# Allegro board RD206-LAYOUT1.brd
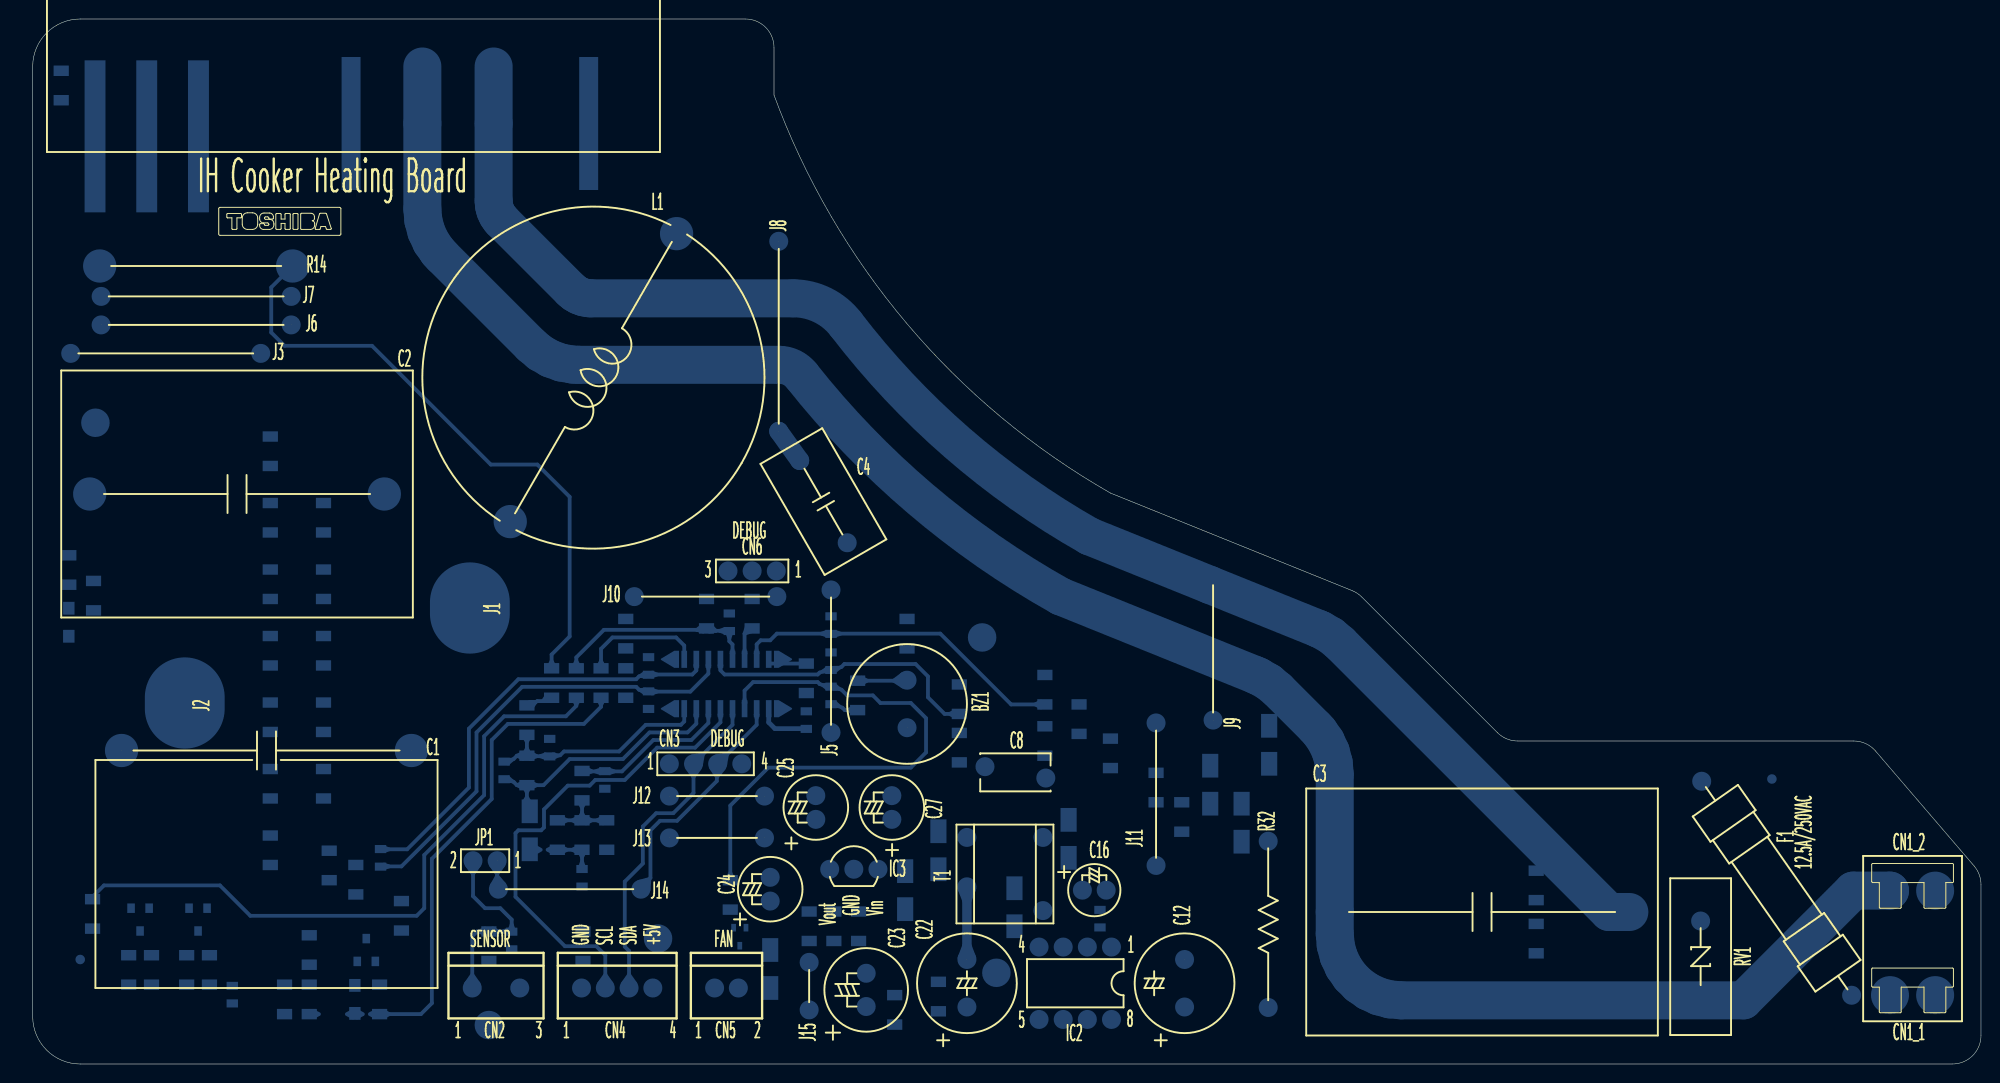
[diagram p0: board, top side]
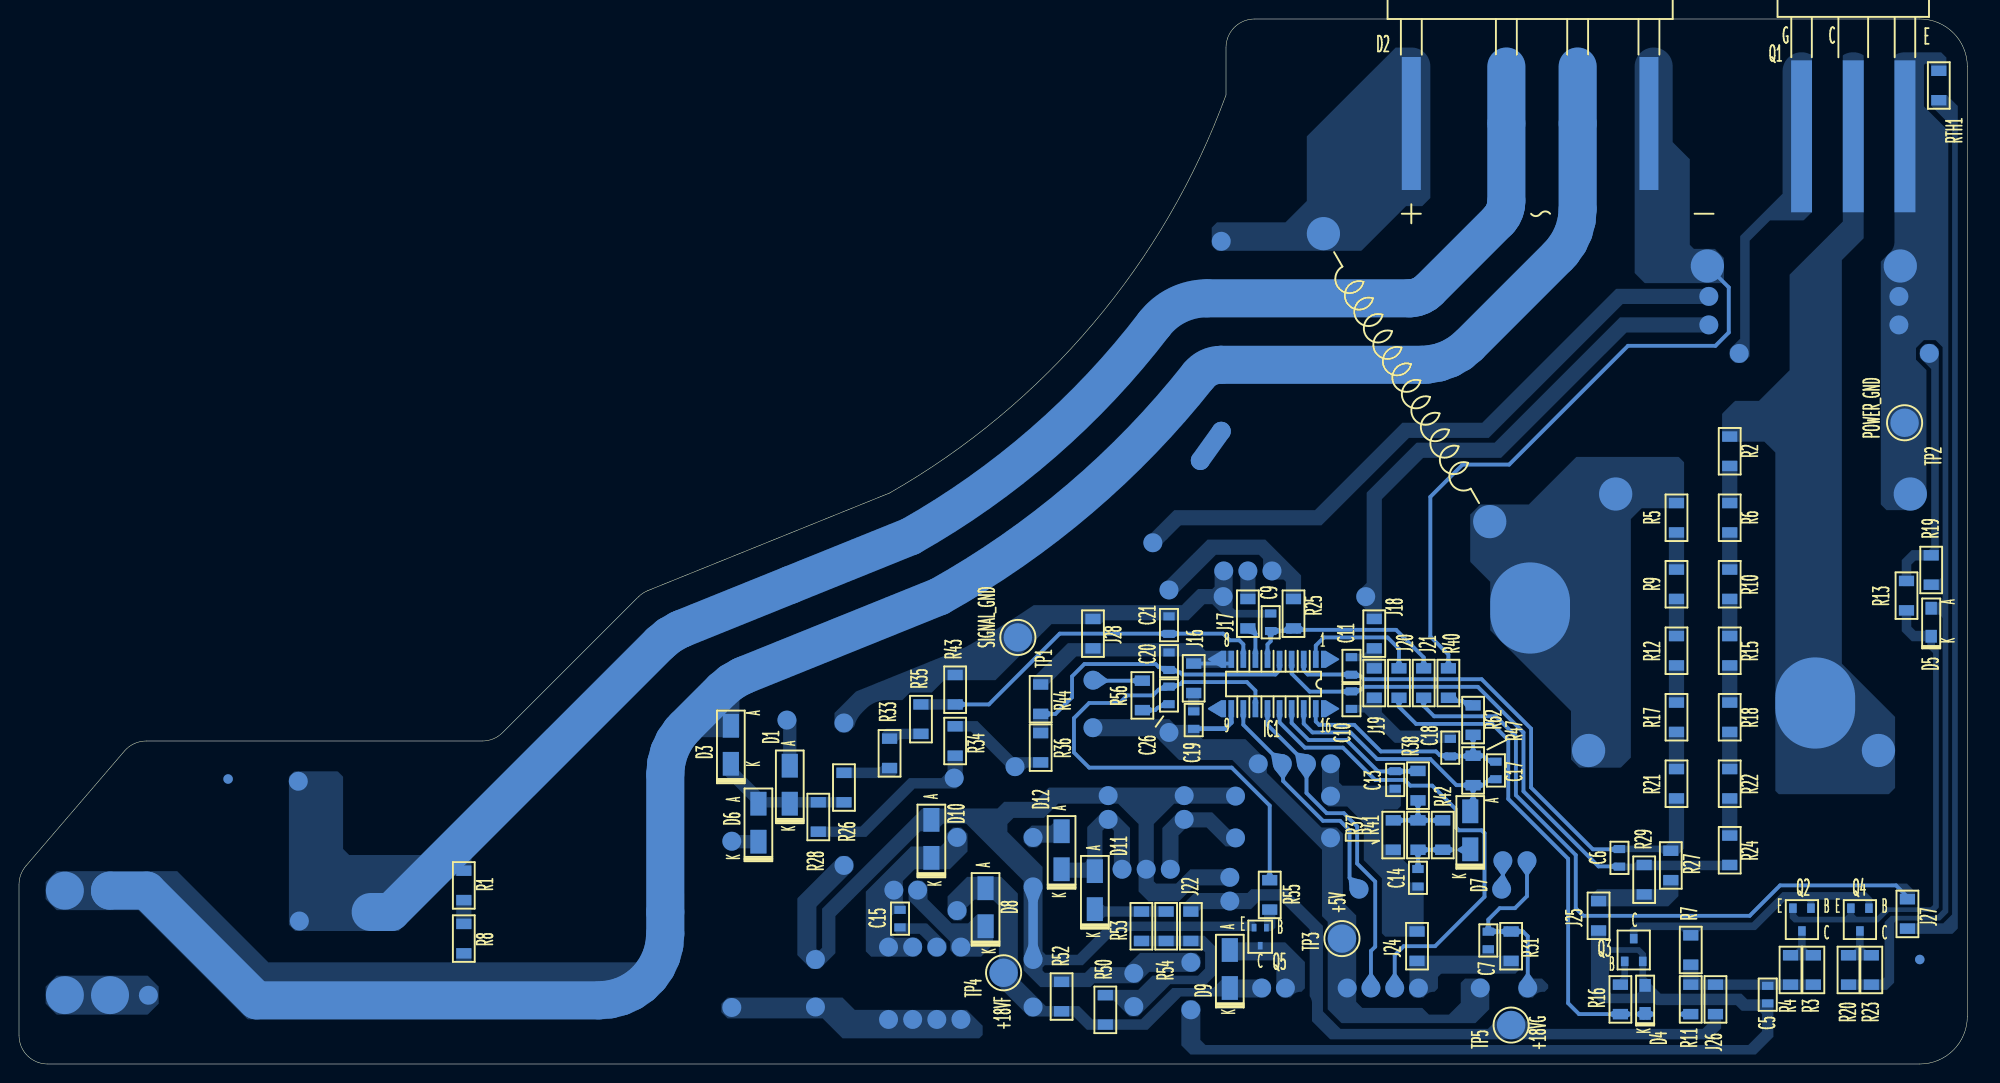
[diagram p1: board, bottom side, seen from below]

Outline 205 x 110 mm; copper layers: TOP, BOTTOM. Coordinates in mm from the lower left corner of the outline.
Outline path: 0,105 arc(1.46,108.54) 5,110 75,110 arc(77.12,109.12) 78,107 78,102 arc(92,77.92) 113.4,60.1 138.83,49.83 arc(139.37,49.55) 139.83,49.17 154.12,34.88 arc(155.09,34.23) 156.24,34 191.62,34 arc(192.87,33.73) 193.9,32.95 204.28,20.84 arc(204.81,19.93) 205,18.89 205,3 arc(204.12,0.88) 202,0 5,0 arc(1.46,1.46) 0,5 0,105

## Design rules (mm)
constraint set DEFAULT: 

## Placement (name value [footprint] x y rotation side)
BZ1  -  [FOOT13801A]  92 37.9 90 top
C1  -  [FOOT13608A]  24.6 33 180 top
C2  -  [FOOT13609A]  21.5 60 180 top
C3  -  [FOOT13609A]  152.5 16 180 top
C4  -  [FOOT13606A]  83.2 59.2 300 top
C5  -  [FOOT6003A]  21 7.3 270 bottom
C6  -  [FOOT6003A]  36.6 21.7 270 bottom
C7  -  [FOOT6003A]  50.4 13 90 bottom
C8  -  [FOOT13607A]  103.4 30.7 180 top
C9  -  [FOOT6003A]  73.3 46.5 90 bottom
C10  -  [FOOT6003A]  64.8 38.3 270 bottom
C11  -  [FOOT6003A]  64.8 41.9 90 bottom
C12  -  [FOOT13601A]  121.2 8.5 90 top
C13  -  [FOOT6003A]  60.2 29.9 270 bottom
C14  -  [FOOT6003A]  57.8 19.6 270 bottom
C15  -  [FOOT6003A]  112.3 15.3 270 bottom
C16  -  [FOOT13603A]  111.7 18.3 0 top
C17  -  [FOOT6003A]  49.6 30.9 90 bottom
C18  -  [FOOT6003A]  54.4 33.3 90 bottom
C19  -  [FOOT6003A]  81.4 36.2 90 bottom
C20  -  [FOOT6003A]  84 42.4 90 bottom
C21  -  [FOOT6003A]  84 46.2 90 bottom
C22  -  [FOOT13601A]  98.3 8.5 90 top
C23  -  [FOOT13604A]  87.7 7.8 90 top
C24  -  [FOOT13605A]  77.6 18.4 90 top
C25  -  [FOOT13605A]  82.4 27 90 top
C26  -  [FOOT6003A]  84 38.8 270 bottom
C27  -  [FOOT13605A]  90.4 27 90 top
CN1_1  -  [FOOT13901A]  197.8 7.25 0 top
CN1_2  -  [FOOT13901A]  197.8 18.25 0 top
CN2  -  [FOOT13910A]  48.75 8 180 top
CN3  -  [FOOT13906A]  70.8 31.6 0 top
CN4  -  [FOOT13904A]  61.5 8 180 top
CN5  -  [FOOT13902A]  73 8 180 top
CN6  -  [FOOT13908A]  75.7 51.9 180 top
D1  -  [FOOT13451A]  123.9 29.4 270 bottom
D2  -  [FOOT13452A]  46 121 180 bottom
D3  -  [FOOT13451A]  130.1 33.6 270 bottom
D4  -  [FOOT4291A]  33.9 6.8 270 bottom
D5  -  [FOOT4291A]  3.8 46.5 270 bottom
D6  -  [FOOT13451A]  127.2 25.4 270 bottom
D7  -  [FOOT13451A]  52.3 24.6 270 bottom
D8  -  [FOOT13451A]  103.3 16.5 270 bottom
D9  -  [FOOT13451A]  77.6 10 270 bottom
D10  -  [FOOT13451A]  109 23.7 270 bottom
D11  -  [FOOT13451A]  91.8 18.3 270 bottom
D12  -  [FOOT13451A]  95.3 22.5 270 bottom
F1  -  [FOOT13701A]  183.5 18.5 125 top
IC1  -  [FOOT2183A]  73 40 0 bottom
IC2  -  [FOOT13001A]  109.7 8.5 180 top
IC3  -  [FOOT13002A]  86.4 20.5 0 top
J1  -  [FOOT13909A]  46 48 0 top
J2  -  [FOOT13909A]  16 38 0 top
J3  -  [FOOT13917A]  24 74.8 180 top
J5  -  [FOOT13915A]  84 34.9 90 top
J6  -  [FOOT13917A]  7.2 77.8 0 top
J7  -  [FOOT13917A]  27.2 80.8 180 top
J8  -  [FOOT13917A]  78.5 86.6 270 top
J9  -  [FOOT13915A]  124.2 51.2 270 top
J10  -  [FOOT13915A]  63.3 49.2 0 top
J11  -  [FOOT13915A]  118.2 35.9 270 top
J12  -  [FOOT13913A]  77 28.2 180 top
J13  -  [FOOT13913A]  77 23.8 180 top
J14  -  [FOOT13915A]  64 18.4 180 top
J15  -  [FOOT13911A]  81.7 10.7 270 top
J16  -  [J16_FOOT4004B]  81.4 40.6 90 bottom
J17  -  [J17_FOOT4004B]  75.7 47.4 90 bottom
J18  -  [J18_FOOT4004B]  62.4 45.3 270 bottom
J19  -  [J19_FOOT4004B]  62.4 40.1 270 bottom
J20  -  [J20_FOOT4004B]  59.8 40.1 270 bottom
J21  -  [J21_FOOT4004B]  57.2 40.1 90 bottom
J22  -  [J22_FOOT4004B]  81.7 14.5 90 bottom
J24  -  [J24_FOOT4004B]  57.9 12.4 270 bottom
J25  -  [J25_FOOT4004B]  38.8 15.6 90 bottom
J26  -  [J26_FOOT4004B]  26.5 6.8 90 bottom
J27  -  [J27_FOOT4004B]  6.3 15.8 90 bottom
J28  -  [J28_FOOT4004B]  92 45.3 270 bottom
JP1  -  [FOOT13905A]  47.6 21.4 180 top
L1  -  [FOOT13301A]  59 72.25 240 top
NOREF  -  []  48.75 8 0 top
NOREF#2  -  []  70.15 6.4 0 top
NOREF#3  -  []  5 5 0 top
NOREF#4  -  []  44.65 6.4 0 top
NOREF#5  -  []  174 -14 0 top
NOREF#6  -  []  191 27 0 top
NOREF#7  -  []  25 103 0 top
NOREF#8  -  []  26 88.7 0 top
NOREF#9  -  []  56.15 6.4 0 top
NOREF#10  -  []  25 103 0 top
NOREF#11  -  []  191 27 0 top
NOREF#12  -  []  5 5 0 top
NOREF#13  -  []  183 30 180 bottom
NOREF#14  -  []  5 11 180 bottom
Q1  -  [FOOT13501A]  12 125 180 bottom
Q2  -  [FOOT5004A]  17.4 15.2 0 bottom
Q3  -  [FOOT5004A]  35.1 12 180 bottom
Q4  -  [FOOT5004A]  11.3 15.2 0 bottom
Q5  -  [FOOT13502A]  74.4 13.4 0 bottom
R1  -  [R1_FOOT4004B]  158.2 18.8 270 bottom
R2  -  [R2_FOOT4004B]  25 64.5 270 bottom
R3  -  [R3_FOOT4004B]  16.2 9.9 90 bottom
R4  -  [R4_FOOT4004B]  18.6 9.9 90 bottom
R5  -  [R5_FOOT4004B]  30.6 57.5 270 bottom
R6  -  [R6_FOOT4004B]  25 57.5 90 bottom
R7  -  [R7_FOOT4004B]  29.1 12 90 bottom
R8  -  [R8_FOOT4004B]  158.2 13.2 270 bottom
R9  -  [R9_FOOT4004B]  30.6 50.5 270 bottom
R10  -  [R10_FOOT4004B]  25 50.5 270 bottom
R11  -  [R11_FOOT4004B]  29.1 6.8 270 bottom
R12  -  [R12_FOOT4004B]  30.6 43.5 270 bottom
R13  -  [R13_FOOT4004B]  6.4 49.3 270 bottom
R14  -  [FOOT13402A]  17.2 84 180 top
R15  -  [R15_FOOT4004B]  25 43.5 270 bottom
R16  -  [R16_FOOT4004B]  36.5 6.8 270 bottom
R17  -  [R17_FOOT4004B]  30.6 36.5 270 bottom
R18  -  [R18_FOOT4004B]  25 36.5 270 bottom
R19  -  [R19_FOOT4004B]  3.8 52 270 bottom
R20  -  [R20_FOOT4004B]  12.5 9.9 270 bottom
R21  -  [R21_FOOT4004B]  30.6 29.5 270 bottom
R22  -  [R22_FOOT4004B]  25 29.5 270 bottom
R23  -  [R23_FOOT4004B]  10.1 9.9 270 bottom
R24  -  [R24_FOOT4004B]  25 22.5 270 bottom
R25  -  [R25_FOOT4004B]  70.9 47.4 270 bottom
R26  -  [R26_FOOT4004B]  118.2 29.1 90 bottom
R27  -  [R27_FOOT4004B]  31.2 20.9 270 bottom
R28  -  [R28_FOOT4004B]  120.9 26 270 bottom
R29  -  [R29_FOOT4004B]  34 19.4 270 bottom
R31  -  [R31_FOOT4004B]  48 12.4 90 bottom
R32  -  [FOOT13401A]  130 14.7 270 top
R33  -  [R33_FOOT4004B]  113.4 32.7 90 bottom
R34  -  [R34_FOOT4004B]  106.5 34 90 bottom
R35  -  [R35_FOOT4004B]  110.1 36.3 90 bottom
R36  -  [R36_FOOT4004B]  97.5 33.3 90 bottom
R37  -  [R37_FOOT4004B]  60.4 24.1 90 bottom
R38  -  [R38_FOOT4004B]  57.8 29.3 90 bottom
R40  -  [R40_FOOT4004B]  54.6 40.1 270 bottom
R41  -  [R41_FOOT4004B]  57.8 24.1 270 bottom
R42  -  [R42_FOOT4004B]  55.2 24.1 270 bottom
R43  -  [R43_FOOT4004B]  106.5 39.4 90 bottom
R44  -  [R44_FOOT4004B]  97.5 38.4 90 bottom
R47  -  [R47_FOOT4004B]  52 30.9 90 bottom
R50  -  [R50_FOOT4004B]  90.7 5.7 90 bottom
R52  -  [R52_FOOT4004B]  95.3 7.1 90 bottom
R53  -  [R53_FOOT4004B]  86.9 14.5 90 bottom
R54  -  [R54_FOOT4004B]  84.3 14.5 90 bottom
R55  -  [R55_FOOT4004B]  73.4 17.8 270 bottom
R56  -  [R56_FOOT4004B]  86.8 38.8 90 bottom
R62  -  [R62_FOOT4004B]  52 36.2 270 bottom
RTH1  -  [FOOT3109A]  3 103 270 bottom
RV1  -  [FOOT13302A]  175.5 11.3 270 top
T1  -  [FOOT13303A]  102.3 20 270 top
TP1  -  [FOOT13998A]  99.9 44.9 180 bottom
TP2  -  [FOOT13998A]  6.6 67.5 180 bottom
TP3  -  [FOOT13998A]  65.8 13.2 180 bottom
TP4  -  [FOOT13998A]  101.4 9.6 180 bottom
TP5  -  [FOOT13998A]  48 4.1 180 bottom

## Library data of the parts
BZ1 = Part13801: alternate symbols: (BZ1_Foot13801A)
C1 = Part13608: alternate symbols: (C1_Foot13608A)
C2 C3 = Part13609: alternate symbols: (C2_Foot13609A,C3_Foot13609A)
C4 = Part13606: alternate symbols: (C4_Foot13606A)
C5-C7 C9-C11 C13-C15 C17-C21 C26 = Part6003: alternate symbols: (T:Foot6003A;B:Foot6003B)
C8 = Part13607: alternate symbols: (C8_Foot13607A)
C12 C22 = Part13601: alternate symbols: (C22_Foot13601A,C12_Foot13601A)
C16 = Part13603: alternate symbols: (C16_Foot13603A)
C23 = Part13604: alternate symbols: (C23_Foot13604A)
C24 C25 C27 = Part13605: alternate symbols: (C24_Foot13605A,C25_Foot13605A,C27_Foot13605A)
CN1_1 CN1_2 = Part13901: alternate symbols: (CN1_1_Foot13901A,CN1_2_Foot13901A)
CN2 = Part13910: alternate symbols: (CN2_Foot13910A)
CN3 = Part13906: alternate symbols: (CN3_Foot13906A)
CN4 = Part13904: alternate symbols: (CN4_Foot13904A)
CN5 = Part13902: alternate symbols: (CN5_Foot13902A)
CN6 = Part13908: alternate symbols: (CN6_Foot13908A)
D1 D3 D6-D12 = Part13451: alternate symbols: (T:Foot13451A;B:Foot13451B,D1_Foot13451B,D3_Foot13451B,D6_Foot13451B,D7_Foot13451B,D8_Foot13451B,D9_Foot13451B,D10_Foot13451B,D11_Foot13451B,D12_Foot13451B)
D2 = Part13452: alternate symbols: (T:Foot13452A;B:Foot13452B,D2_Foot13452B)
D4 D5 = Part4291: alternate symbols: (T:Foot4291A;B:Foot4291B,D4_Foot4291B,D5_Foot4291B)
F1 = Part13701: alternate symbols: (F1_Foot13701A)
IC1 = Part2183: alternate symbols: (T:Foot2183A;B:Foot2183B,IC1_Foot2183B)
IC2 = Part13001: alternate symbols: (IC2_Foot13001A)
IC3 = Part13002: alternate symbols: (IC3_Foot13002A)
J1 J2 = Part13909: alternate symbols: (J1_Foot13909A,J2_Foot13909A)
J3 J6-J8 = Part13917: alternate symbols: (J3_Foot13917A,J6_Foot13917A,J7_Foot13917A,J8_Foot13917A)
J5 J9-J11 J14 = Part13915: alternate symbols: (J5_Foot13915A,J9_Foot13915A,J10_Foot13915A,J11_Foot13915A,J14_Foot13915A)
J12 J13 = Part13913: alternate symbols: (J12_Foot13913A,J13_Foot13913A)
J15 = Part13911: alternate symbols: (J15_Foot13911A)
J16-J22 J24-J28 R1-R13 R15-R29 R31 R33-R38 R40-R44 R47 R50 R52-R56 R62 = Part4004
JP1 = Part13905: alternate symbols: (JP1_Foot13905A)
L1 = Part13301: alternate symbols: (L1_Foot13301A)
Q1 = Part13501: alternate symbols: (T:Foot13501A;B:Foot13501B,Q1_Foot13501B)
Q2-Q4 = Part5004: alternate symbols: (T:Foot5004A;B:Foot5004B,Q2_Foot5004B,Q3_Foot5004B,Q4_Foot5004B)
Q5 = Part13502: alternate symbols: (T:Foot13502A;B:Foot13502B,Q5_Foot13502B)
R14 = Part13402: alternate symbols: (R14_Foot13402A)
R32 = Part13401: alternate symbols: (R32_Foot13401A)
RTH1 = Part3109: alternate symbols: (T:Foot3109A;B:Foot3109B,RTH1_Foot3109B)
RV1 = Part13302: alternate symbols: (RV1_Foot13302A)
T1 = Part13303: alternate symbols: (T1_Foot13303A)
TP1-TP5 = Part13998: alternate symbols: (T:Foot13998A;B:Foot13998B,TP1_Foot13998B,TP2_Foot13998B,TP3_Foot13998B,TP4_Foot13998B,TP5_Foot13998B)

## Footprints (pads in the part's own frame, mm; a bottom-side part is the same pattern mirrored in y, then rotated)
FOOT2183A
  rect 0.6x1.8 smd: 1(-4.445,-2.6) 2(-3.175,-2.6) 3(-1.905,-2.6) 4(-0.635,-2.6) 5(0.635,-2.6) 6(1.905,-2.6) 7(3.175,-2.6) 8(4.445,-2.6) 9(4.445,2.6) 10(3.175,2.6) 11(1.905,2.6) 12(0.635,2.6) 13(-0.635,2.6) 14(-1.905,2.6) 15(-3.175,2.6) 16(-4.445,2.6)
FOOT3109A
  rect 1.1x1.6 smd: 1(-1.55,0) 2(1.55,0)
FOOT4291A
  rect 1.35x1.2 smd: A(-1.475,0) C(1.475,0)
FOOT5004A
  rect 0.8x1 smd: 1(-0.95,-1.2) 2(0.95,-1.2) 3(0,1.2)
FOOT6003A
  rect 0.85x1.2 smd: 1(-0.925,0) 2(0.925,0)
FOOT13001A
  round 0.01 hole 0.9: 1(-3.81,-3.81) 2(-1.27,-3.81) 3(1.27,-3.81) 4(3.81,-3.81) 5(3.81,3.81) 6(1.27,3.81) 7(-1.27,3.81) 8(-3.81,3.81)
FOOT13002A
  round 0.01 hole 1: 1(-2.54,0) 2(0,0) 3(2.54,0)
FOOT13301A
  round 0.01 hole 1.3: 1(-17.5,0) 2(17.5,0)
FOOT13302A
  round 0.01 hole 1: 1(-3.75,0) 2(3.75,0)
FOOT13303A
  round 0.01 hole 0.9: 1(-3.85,-4) 3(1.35,-4) 5(3.85,4) 8(-3.85,4)
FOOT13401A
  round 0.01 hole 0.9: 1(-8.75,0) 2(8.75,0)
FOOT13402A
  round 0.01 hole 1.3: 1(-10.15,0) 2(10.15,0)
FOOT13451A
  rect 2.5x1.7 smd: A(-2,0) C(2,0)
FOOT13452A
  rect 2x14 smd: 1(-12.5,-22) 2(-2.5,-22) 3(5,-22) 4(12.5,-22)
FOOT13501A
  rect 2.2x16 smd: 1(-5.44,-27.35) 2(0,-27.35) 3(5.44,-27.35)
FOOT13502A
  rect 0.5x0.8 smd: 1(-0.65,-0.95) 2(0.65,-0.95) 3(0,0.95)
FOOT13601A
  round 0.01 hole 0.9: 1(-2.5,0) 2(2.5,0)
FOOT13603A
  round 0.01 hole 0.9: 1(-1.25,0) 2(1.25,0)
FOOT13604A
  round 0.01 hole 0.9: 1(-1.75,0) 2(1.75,0)
FOOT13605A
  round 0.01 hole 0.9: 1(-1.25,0) 2(1.25,0)
FOOT13606A
  round 0.01 hole 0.9: 1(-5,0) 2(5,0)
FOOT13607A
  round 0.01 hole 0.9: 1(-3.2,0.6) 2(3.2,-0.6)
FOOT13608A
  round 0.01 hole 1.3: 1(-15.25,0) 2(15.25,0)
FOOT13609A
  round 0.01 hole 1.3: 1(-15.5,0) 2(15.5,0)
FOOT13701A
  round 0.01 hole 1: 1(-13.75,0) 2(13.75,0)
FOOT13801A
  round 0.01 hole 0.9: 1(-2.5,0) 2(2.5,0)
FOOT13901A
  round 0.01 hole 1.7: 1(-2.375,0) 2(2.375,0)
FOOT13902A
  round 0.01 hole 1: 1(1.25,0) 2(-1.25,0)
FOOT13904A
  round 0.01 hole 1: 1(3.75,0) 2(1.25,0) 3(-1.25,0) 4(-3.75,0)
FOOT13905A
  round 0.01 hole 1: 1(-1.27,0) 2(1.27,0)
FOOT13906A
  round 0.01 hole 1: 1(-3.81,0) 2(-1.27,0) 3(1.27,0) 4(3.81,0)
FOOT13908A
  round 0.01 hole 1: 1(-2.54,0) 2(0,0) 3(2.54,0)
FOOT13909A
  round 0.01 hole 1.505: 1(0,0)
FOOT13910A
  round 0.01 hole 1: 1(2.5,0) 3(-2.5,0)
FOOT13911A
  round 0.01 hole 1: 1(0,0) 2(5,0)
FOOT13913A
  round 0.01 hole 1: 1(0,0) 2(10,0)
FOOT13915A
  round 0.01 hole 1: 1(0,0) 2(15,0)
FOOT13917A
  round 0.01 hole 1: 1(0,0) 2(20,0)
FOOT13998A
  round 3 smd: 1(0,0)
J16_FOOT4004B
  rect 1.1x1.6 smd: 1(-1.55,0) 2(1.55,0)
J17_FOOT4004B
  rect 1.1x1.6 smd: 1(-1.55,0) 2(1.55,0)
J18_FOOT4004B
  rect 1.1x1.6 smd: 1(-1.55,0) 2(1.55,0)
J19_FOOT4004B
  rect 1.1x1.6 smd: 1(-1.55,0) 2(1.55,0)
J20_FOOT4004B
  rect 1.1x1.6 smd: 1(-1.55,0) 2(1.55,0)
J21_FOOT4004B
  rect 1.1x1.6 smd: 1(-1.55,0) 2(1.55,0)
J22_FOOT4004B
  rect 1.1x1.6 smd: 1(-1.55,0) 2(1.55,0)
J24_FOOT4004B
  rect 1.1x1.6 smd: 1(-1.55,0) 2(1.55,0)
J25_FOOT4004B
  rect 1.1x1.6 smd: 1(-1.55,0) 2(1.55,0)
J26_FOOT4004B
  rect 1.1x1.6 smd: 1(-1.55,0) 2(1.55,0)
J27_FOOT4004B
  rect 1.1x1.6 smd: 1(-1.55,0) 2(1.55,0)
J28_FOOT4004B
  rect 1.1x1.6 smd: 1(-1.55,0) 2(1.55,0)
R1_FOOT4004B
  rect 1.1x1.6 smd: 1(-1.55,0) 2(1.55,0)
R2_FOOT4004B
  rect 1.1x1.6 smd: 1(-1.55,0) 2(1.55,0)
R3_FOOT4004B
  rect 1.1x1.6 smd: 1(-1.55,0) 2(1.55,0)
R4_FOOT4004B
  rect 1.1x1.6 smd: 1(-1.55,0) 2(1.55,0)
R5_FOOT4004B
  rect 1.1x1.6 smd: 1(-1.55,0) 2(1.55,0)
R6_FOOT4004B
  rect 1.1x1.6 smd: 1(-1.55,0) 2(1.55,0)
R7_FOOT4004B
  rect 1.1x1.6 smd: 1(-1.55,0) 2(1.55,0)
R8_FOOT4004B
  rect 1.1x1.6 smd: 1(-1.55,0) 2(1.55,0)
R9_FOOT4004B
  rect 1.1x1.6 smd: 1(-1.55,0) 2(1.55,0)
R10_FOOT4004B
  rect 1.1x1.6 smd: 1(-1.55,0) 2(1.55,0)
R11_FOOT4004B
  rect 1.1x1.6 smd: 1(-1.55,0) 2(1.55,0)
R12_FOOT4004B
  rect 1.1x1.6 smd: 1(-1.55,0) 2(1.55,0)
R13_FOOT4004B
  rect 1.1x1.6 smd: 1(-1.55,0) 2(1.55,0)
R15_FOOT4004B
  rect 1.1x1.6 smd: 1(-1.55,0) 2(1.55,0)
R16_FOOT4004B
  rect 1.1x1.6 smd: 1(-1.55,0) 2(1.55,0)
R17_FOOT4004B
  rect 1.1x1.6 smd: 1(-1.55,0) 2(1.55,0)
R18_FOOT4004B
  rect 1.1x1.6 smd: 1(-1.55,0) 2(1.55,0)
R19_FOOT4004B
  rect 1.1x1.6 smd: 1(-1.55,0) 2(1.55,0)
R20_FOOT4004B
  rect 1.1x1.6 smd: 1(-1.55,0) 2(1.55,0)
R21_FOOT4004B
  rect 1.1x1.6 smd: 1(-1.55,0) 2(1.55,0)
R22_FOOT4004B
  rect 1.1x1.6 smd: 1(-1.55,0) 2(1.55,0)
R23_FOOT4004B
  rect 1.1x1.6 smd: 1(-1.55,0) 2(1.55,0)
R24_FOOT4004B
  rect 1.1x1.6 smd: 1(-1.55,0) 2(1.55,0)
R25_FOOT4004B
  rect 1.1x1.6 smd: 1(-1.55,0) 2(1.55,0)
R26_FOOT4004B
  rect 1.1x1.6 smd: 1(-1.55,0) 2(1.55,0)
R27_FOOT4004B
  rect 1.1x1.6 smd: 1(-1.55,0) 2(1.55,0)
R28_FOOT4004B
  rect 1.1x1.6 smd: 1(-1.55,0) 2(1.55,0)
R29_FOOT4004B
  rect 1.1x1.6 smd: 1(-1.55,0) 2(1.55,0)
R31_FOOT4004B
  rect 1.1x1.6 smd: 1(-1.55,0) 2(1.55,0)
R33_FOOT4004B
  rect 1.1x1.6 smd: 1(-1.55,0) 2(1.55,0)
R34_FOOT4004B
  rect 1.1x1.6 smd: 1(-1.55,0) 2(1.55,0)
R35_FOOT4004B
  rect 1.1x1.6 smd: 1(-1.55,0) 2(1.55,0)
R36_FOOT4004B
  rect 1.1x1.6 smd: 1(-1.55,0) 2(1.55,0)
R37_FOOT4004B
  rect 1.1x1.6 smd: 1(-1.55,0) 2(1.55,0)
R38_FOOT4004B
  rect 1.1x1.6 smd: 1(-1.55,0) 2(1.55,0)
R40_FOOT4004B
  rect 1.1x1.6 smd: 1(-1.55,0) 2(1.55,0)
R41_FOOT4004B
  rect 1.1x1.6 smd: 1(-1.55,0) 2(1.55,0)
R42_FOOT4004B
  rect 1.1x1.6 smd: 1(-1.55,0) 2(1.55,0)
R43_FOOT4004B
  rect 1.1x1.6 smd: 1(-1.55,0) 2(1.55,0)
R44_FOOT4004B
  rect 1.1x1.6 smd: 1(-1.55,0) 2(1.55,0)
R47_FOOT4004B
  rect 1.1x1.6 smd: 1(-1.55,0) 2(1.55,0)
R50_FOOT4004B
  rect 1.1x1.6 smd: 1(-1.55,0) 2(1.55,0)
R52_FOOT4004B
  rect 1.1x1.6 smd: 1(-1.55,0) 2(1.55,0)
R53_FOOT4004B
  rect 1.1x1.6 smd: 1(-1.55,0) 2(1.55,0)
R54_FOOT4004B
  rect 1.1x1.6 smd: 1(-1.55,0) 2(1.55,0)
R55_FOOT4004B
  rect 1.1x1.6 smd: 1(-1.55,0) 2(1.55,0)
R56_FOOT4004B
  rect 1.1x1.6 smd: 1(-1.55,0) 2(1.55,0)
R62_FOOT4004B
  rect 1.1x1.6 smd: 1(-1.55,0) 2(1.55,0)

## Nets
+5V_A: BZ1.1 C19.1 CN2.3 CN3.4 CN4.4 IC1.9 J5.1 J13.2 TP3.1
+5V_B: CN6.3 J5.2 R25.1
+18VF: C22.1 CN5.2 D8.A D9.C R50.1 R52.1 T1.5 TP4.1
+18VG_A: C5.1 J26.2 R3.1 R4.1 R7.1 R11.1
+18VG_B: C24.1 J22.2 J26.1 TP5.1
+18VG_C: C23.1 J22.1 R50.2 R53.1 R54.1
GND_POWER: C2.2 D5.A J6.1 J7.2 Q1.3 R14.2 R19.2 R20.2 R23.2 RTH1.1 TP2.1
GND_SIGNAL: J6.2 J10.1 J18.1
GND_SIGNAL_A: C9.2 C21.2 CN6.1 J10.2 J11.1 J28.1 R43.2 TP1.1
GND_SIGNAL_B: C12.2 C22.2 C23.2 C24.2 C25.2 C27.2 D10.A IC3.2 J11.2 J12.1 J15.1 Q5.2 R52.2 T1.3
GND_SIGNAL_C: C13.2 C14.2 CN3.1 J12.2 J24.1 R37.1
GND_SIGNAL_D: C7.1 CN4.1 J24.2 R31.1
GND_SIGNAL_E: C5.2 D4.A J15.2 J25.1 Q3.2
GND_SIGNAL_F: J25.2 R27.2 R29.2
GND_SIGNAL_G: C11.2 J18.2 J19.1
GND_SIGNAL_H: C10.2 C18.2 J19.2
GND_SIGNAL_I: C20.2 IC1.8 J16.2 J28.2 R44.2
SCL_H: CN4.2 IC1.13
SDA_H: CN3.2 CN4.3 IC1.12
N15968: CN1_1.1 CN1_1.2 F1.1
N15972: C3.1 D2.2 F1.2 J9.1 R1.1 RV1.1
N16070: C1.1 C2.1 J1.1 L1.2 R5.1
N16078: C1.2 J2.1 Q1.2 R2.1
N16406: C3.2 CN1_2.1 CN1_2.2 D2.3 D3.A R8.2 RV1.2
N16414: J3.1 Q1.1
N16590: D1.C D3.C D6.A R26.1 R28.1
N23336: R1.2 R8.1
N23663: D6.C R32.1
N24888: D5.C Q2.2 Q4.2 R13.2
N24902: Q2.3 R3.2 R4.2
N24906: Q4.3 R20.1 R23.1
N24910: Q2.1 Q3.3 Q4.1 R7.2
N25221: J3.2 R13.1 R19.1
N27035: Q3.1 R16.1
N27227: D4.C J20.2 R11.2 R16.2
N419198: R5.2 R9.1
N419202: R9.2 R12.1
N419206: R12.2 R17.1
N419210: R17.2 R21.1
N419214: C6.1 C11.1 IC1.2 R21.2 R27.1
N419378: R10.2 R15.1
N419402: R15.2 R18.1
N419426: R18.2 R22.1
N419540: R22.2 R24.1
N419564: C6.2 C10.1 IC1.3 R24.2 R29.1
N420408: D2.1 J8.1 L1.1
N420417: D2.4 R14.1 R40.1
N422649: C13.1 IC1.14 R38.2
N424573: R26.2 R33.1
N424617: R33.2 R35.1
N424661: C8.1 R28.2 R34.1
N424705: C8.2 R34.2 R36.1
N424749: C20.1 IC1.4 R36.2 R44.1
N424773: C21.1 IC1.7 R35.2 R43.1
N427169: C27.1 D11.A D12.C IC3.3
N427204: D12.A T1.1
N427457: C25.1 IC3.1 J13.1
N428631: IC1.1 J20.1
N431073: Q5.1 R55.2
N431093: C26.1 IC1.11 R55.1
N431152: CN5.1 D9.A Q5.3
N438066: C12.1 IC2.5 IC2.6 IC2.7 IC2.8 R32.2
N438142: C15.1 C16.2 D10.C IC2.1 IC2.2 T1.8
N438152: C15.2 IC2.3
N438200: C16.1 D8.C IC2.4
N440867: D11.C R53.2 R54.2
N447487: R37.2 R38.1 R41.1 R42.1
N449687: C17.1 D7.A IC1.15 R47.1
N452598: C17.2 C18.1 IC1.16 R47.2 R62.2
N452604: R40.2 R62.1
N456904: J27.1 RTH1.2
N456909: C9.1 IC1.5 J21.2 R25.2
N457222: J21.1 J27.2
N458614: CN3.3 IC1.10 J14.1
N458626: C7.2 CN2.1 JP1.2 R31.2
N459420: IC1.6 J17.1
N466829: C14.1 D7.C R41.2 R42.2
N469207: R6.1 R10.1
N469217: R2.2 R6.2
N493941: CN6.2 J17.2
N504842: C4.2 J7.1
N517870: J14.2 JP1.1
N611853: C26.2 R56.1
N611857: BZ1.2 R56.2
N674486: D1.A J9.2
N675465: C4.1 J8.2
N682614: C19.2 J16.1

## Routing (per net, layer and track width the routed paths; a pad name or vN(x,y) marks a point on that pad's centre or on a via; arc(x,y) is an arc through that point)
+5V_A: length 5.1
  BOTTOM w0.5: 77.44,36.8 77.44,35.95 78.1,35.3 81.4,35.3
GND_SIGNAL_B: length 7.6
  BOTTOM w1: T1.3 C22.2
GND_SIGNAL_I: length 3.7
  BOTTOM w0.4: 81.15,42.15 77.44,42.15
SCL_H: length 50.5
  BOTTOM w0.4: 72.36,36.8 72.36,35.97 69.7,33.3 65.7,33.3 62.3,29.9 59.2,29.9 58.6,29.3 56.3,29.3 53.8,26.8 53.8,24.9 53.5,24.6 51.1,24.6 50.8,24.3 50.8,17.6 56,12.4 59.3,12.4 60.25,11.45 CN4.2
SDA_H: length 34.7
  BOTTOM w0.4: CN4.3 62.75,11.9 62.3,12.35 62.3,19.2 64.2,21.1 64.2,25 65.6,26.4 67.4,26.4 69.53,28.53 CN3.2 73.64,35.7 73.64,36.8
N15972: length 161.9
  BOTTOM w4: C3.1 165.86,16 137.56,44.29 136.63,45.08 135.57,45.69 135.23,45.84 123.88,50.42 111.2,55.54 arc(97.26,65.41) 85.57,77.85 arc(83.11,79.88) 80.01,80.6 58.74,80.6 58.48,80.61 57.97,80.7 57.47,80.88 57.02,81.14 56.62,81.48 49.38,88.72 49.2,88.91 48.9,89.34 48.68,89.82 48.55,90.32 48.5,90.84 D2.2 48.5,105
N16406: length 219.2
  BOTTOM w4: 41,105 D2.3 41,90 41.11,88.78 41.42,87.61 41.94,86.5 42.64,85.5 43.05,85.05 52.45,75.65 53.38,74.87 54.44,74.26 55.59,73.84 56.79,73.63 57.4,73.6 78.55,73.6 arc(79.85,73.3) 80.9,72.46 arc(93.39,59.5) 108.16,49.22 128.68,40.93 129.02,40.79 130.07,40.18 131.01,39.39 134.95,35.45 135.36,35 136.06,34 136.58,32.89 136.89,31.72 137,30.5 C3.2 137,13.7 137.11,12.48 137.42,11.31 137.94,10.2 138.64,9.2 139.5,8.34 140.5,7.64 141.61,7.12 142.78,6.81 144,6.7 180,6.7 191.55,18.25 CN1_2.1
N27227: length 49.9
  BOTTOM w0.4: J20.2 59.8,37.6 58,35.8 50,35.8 48.3,34.1 48.3,27.9 42,21.6 42,6.4 40.85,5.25 36.75,5.25
N419214: length 44.3
  BOTTOM w0.4: 36.9,22.6 39.4,22.6 45.9,29.1 45.9,35.3 51.1,40.5 63.5,40.5 63.8,40.8 64.5,41 ; 65.1,41 69.4,41 69.83,41.42 69.83,42
N419564: length 46.9
  BOTTOM w0.4: 64.5,39.2 63.8,39.4 63.5,39.7 51.5,39.7 46.7,34.9 46.7,28.7 38.8,20.8 36.9,20.8 ; 65.1,39.2 69.2,39.2 71.09,41.09 71.09,42
N420417: length 65.3
  BOTTOM w0.4: R40.1 54.6,43.1 56.5,45 56.5,59.7 53.1,63.1 48.2,63.1 35.7,75.6 26.5,75.6 25.1,77 25.1,81.75 R14.1
N422649: length 15.3
  BOTTOM w0.4: 59.8,30.8 58.82,30.8 58.05,30.85 ; 71.09,36.8 71.09,35.9 69.3,34.1 65.3,34.1 62,30.8 60.6,30.8
N424749: length 28.8
  BOTTOM w0.4: 83.7,41.5 82.8,41.2 82.6,41 72.8,41 72.36,41.44 72.36,42 ; 84.3,41.5 85.1,41.8 85.4,42.1 92.9,42.1 94.2,40.8 94.2,38.6 95.95,36.85 97.25,36.85
N424773: length 33.8
  BOTTOM w0.4: 76.17,43.2 76.17,44.17 76.6,44.6 77.6,44.6 78.3,45.3 83.6,45.3 ; 84.4,45.3 95.5,45.3 102.95,37.85 106.25,37.85
N428631: length 12.5
  BOTTOM w0.4: J20.1 59.8,43.7 61,44.9 67.7,44.9 68.56,44.05 68.56,43.2
N431093: length 56
  BOTTOM w0.4: R55.1 73.4,27.2 77.4,31.2 92.4,31.2 94,32.8 94,36.4 92.4,38 89.2,38 88.4,38.8 85.7,38.8 85.1,39.4 84.3,39.7 ; 83.7,39.7 82.8,40 82.6,40.2 75.8,40.2 74.91,39.3 74.91,38
N447487: length 6.3
  BOTTOM w0.4: R41.1 R38.1 ; 57.55,25.65 55.45,25.65 ; 58.05,25.65 60.15,25.65
N449687: length 25.1
  BOTTOM w0.4: 49.9,30 50.6,29.7 50.95,29.35 51.75,29.35 ; R47.1 52,27.5 ; 69.83,36.8 69.83,35.83 68.9,34.9 64.9,34.9 62.1,32.1 56.5,32.1 53.75,29.35 52.25,29.35
N452598: length 22.1
  BOTTOM w0.4: 54.7,32.4 55.5,32.5 55.91,32.9 61.7,32.9 64.5,35.7 68.2,35.7 68.56,36.05 68.56,36.8 ; 49.9,31.8 50.6,32.1 50.95,32.45 51.75,32.45 ; R47.2 R62.2 ; 54,32.4 53.02,32.4 52.25,32.45
N452604: length 2.3
  BOTTOM w0.4: 52.25,37.75 53.1,38.2 53.7,38.2 54.35,38.55
N456909: length 19.9
  BOTTOM w0.4: J21.2 57.2,42.8 60.1,45.7 69.89,45.7 70.65,45.85 ; 72.9,45.6 71.88,45.6 71.15,45.85 ; 73.3,45.4 73.3,44.5 73.64,44.16 73.64,43.2
N457222: length 69.9
  BOTTOM w0.4: J21.1 57.2,37.7 56.1,36.6 49.6,36.6 47.5,34.5 47.5,28.3 41.2,22 41.2,16.4 40.4,15.6 22.9,15.6 19.7,18.8 7.5,18.8 6.3,17.6 J27.2
N458614: length 24.4
  BOTTOM w0.4: 76.17,36.8 76.17,35.7 CN3.3 71.98,29.78 67.8,25.6 66,25.6 65,24.6 65,19.6 J14.1
N458626: length 18.9
  BOTTOM w0.4: CN2.1 46.25,13.45 46.75,13.95 47.75,13.95 ; 50.4,14.1 50.4,15.2 49.2,16.4 47.6,16.4 46.33,17.67 JP1.2 ; 48.25,13.95 50.05,13.95
N459420: length 2.9
  BOTTOM w0.4: 74.91,43.2 74.91,45.3 75.45,45.85
N466829: length 3.9
  BOTTOM w0.4: 55.45,22.55 57.55,22.55 ; 57.8,20.7 R41.2
N517870: length 3
  BOTTOM w0.4: J14.2 48.87,19.79 JP1.1
N611853: length 2.4
  BOTTOM w0.4: 86.55,37.25 85.45,37.25 85.2,37.5 84.3,37.9
N611857: length 5
  BOTTOM w0.4: 87.05,40.35 90.6,40.35 BZ1.2
N675465: length 3.8
  BOTTOM w2: J8.2 C4.1

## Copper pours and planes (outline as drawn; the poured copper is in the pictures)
+5V_A on BOTTOM: outline of 85 points within 50.3,4.3 92.9,36.3
+5V_B on BOTTOM: 70.2,48.4 70.13,48.43 70.1,48.5 70.1,51.4 70.11,51.44 70.13,51.47 73.83,55.17 73.86,55.19 73.9,55.2 79.9,55.2 79.94,55.19 79.97,55.17 84.77,50.37 84.79,50.34 84.8,50.3 84.8,49.6 84.79,49.56 84.77,49.53 84.37,49.13 84.34,49.11 84.3,49.1 83.6,49.1 83.56,49.11 83.53,49.13 79.06,53.6 74.54,53.6 74.1,53.16 74.1,51.8 74.09,51.76 74.07,51.73 73.37,51.03 73.34,51.01 73.3,51 71.94,51 71.7,50.76 71.7,48.5 71.67,48.43 71.6,48.4
+18VF on BOTTOM: 86.3,3.6 86.26,3.61 86.23,3.63 82.76,7.1 78.34,7.1 78.27,7.03 78.24,7.01 78.2,7 73.9,7 73.86,7.01 73.83,7.03 73.33,7.53 73.31,7.56 73.3,7.6 73.3,8.4 73.31,8.44 73.33,8.47 73.73,8.87 73.76,8.89 73.8,8.9 78.4,8.9 78.44,8.89 78.47,8.87 79.34,8 83.6,8 83.64,7.99 83.67,7.97 86.94,4.7 92.06,4.7 93.43,6.07 93.46,6.09 93.5,6.1 96.96,6.1 99.9,9.04 99.9,17.9 99.91,17.94 99.93,17.97 101.63,19.67 101.66,19.69 101.7,19.7 105.2,19.7 105.24,19.69 105.27,19.67 107.27,17.67 107.29,17.64 107.3,17.6 107.3,15.8 107.29,15.76 107.27,15.73 106.67,15.13 106.64,15.11 106.6,15.1 105.9,15.1 105.86,15.11 105.83,15.13 105.33,15.63 105.31,15.66 105.3,15.7 105.3,16.46 104.46,17.3 102.54,17.3 101.9,16.66 101.9,11.14 102.57,10.47 102.59,10.44 102.6,10.4 102.6,8.9 102.59,8.86 102.57,8.83 98.77,5.03 98.74,5.01 98.7,5 94.04,5 92.67,3.63 92.64,3.61 92.6,3.6
+18VG_B on BOTTOM: 27.1,2.6 27.06,2.61 27.03,2.63 25.93,3.73 25.91,3.76 25.9,3.8 25.9,5.6 25.93,5.67 26,5.7 27,5.7 27.07,5.67 27.1,5.6 27.1,4.44 27.84,3.7 45.56,3.7 47.13,5.27 47.16,5.29 47.2,5.3 48.8,5.3 48.84,5.29 48.87,5.27 50.44,3.7 65.96,3.7 67.8,5.54 67.8,14.5 67.81,14.54 67.83,14.57 71.63,18.37 71.66,18.39 71.7,18.4 75.3,18.4 75.34,18.39 75.37,18.37 75.74,18 81.3,18 81.34,17.99 81.37,17.97 82.47,16.87 82.49,16.84 82.5,16.8 82.5,15.6 82.47,15.53 82.4,15.5 81,15.5 80.93,15.53 80.9,15.6 80.9,16.06 80.66,16.3 75.4,16.3 75.36,16.31 75.33,16.33 74.46,17.2 72.24,17.2 69.2,14.16 69.2,7.17 69.2,7.14 69.01,6.77 68.95,6.4 68.95,4.55 68.94,4.51 68.92,4.48 67.07,2.63 67.04,2.61 67,2.6
+18VG_C on BOTTOM: 87.3,5 87.26,5.01 87.23,5.03 83.86,8.4 80.1,8.4 80.06,8.41 80.03,8.43 79.03,9.43 79.01,9.46 79,9.5 79,12.2 79.01,12.24 79.03,12.27 80.23,13.47 80.26,13.49 80.3,13.5 87.6,13.5 87.67,13.47 87.7,13.4 87.7,12.5 87.67,12.43 87.6,12.4 80.84,12.4 80.2,11.76 80.2,10.04 80.94,9.3 85.7,9.3 85.74,9.29 85.77,9.27 87.24,7.8 91.4,7.8 91.47,7.77 91.5,7.7 91.5,6.8 91.47,6.73 91.4,6.7 89.84,6.7 88.17,5.03 88.14,5.01 88.1,5
GND_POWER on BOTTOM: outline of 101 points within 2,7.8 13.3,106.5
GND_SIGNAL on BOTTOM: 61.7,46.3 61.63,46.33 61.6,46.4 61.6,59.46 57.26,63.8 49.1,63.8 49.06,63.81 49.03,63.83 35.86,77 26.8,77 26.76,77.01 26.73,77.03 26.43,77.33 26.41,77.36 26.4,77.4 26.4,78.2 26.41,78.24 26.43,78.27 26.73,78.57 26.76,78.59 26.8,78.6 36.5,78.6 36.54,78.59 36.57,78.57 49.74,65.4 57.9,65.4 57.94,65.39 57.97,65.37 63.17,60.17 63.19,60.14 63.2,60.1 63.2,50.64 63.87,49.97 63.89,49.94 63.9,49.9 63.9,48.5 63.89,48.46 63.87,48.43 63.2,47.76 63.2,46.4 63.17,46.33 63.1,46.3
GND_SIGNAL_A on BOTTOM: 117.8,34.9 117.76,34.91 117.73,34.93 117.13,35.53 117.11,35.55 116.79,36.34 116.29,36.99 115.89,37.39 114.89,38.06 113.7,38.3 112.1,38.3 112.06,38.31 112.03,38.33 111.26,39.1 109,39.1 108.96,39.11 108.93,39.13 107.66,40.4 102.3,40.4 102.26,40.41 102.23,40.43 96.36,46.3 91.2,46.3 91.16,46.31 91.13,46.33 90.76,46.7 82,46.7 81.96,46.71 81.93,46.73 80.26,48.4 79.44,48.4 78.07,47.03 78.04,47.01 78,47 72.8,47 72.73,47.03 72.7,47.1 72.7,47.7 72.73,47.77 72.8,47.8 77.06,47.8 77.3,48.04 77.3,52 77.31,52.04 77.33,52.07 77.83,52.57 77.86,52.59 77.9,52.6 78.6,52.6 78.64,52.59 78.67,52.57 79.17,52.07 79.19,52.04 79.2,52 79.2,50.24 79.44,50 80.9,50 80.94,49.99 80.97,49.97 82.64,48.3 98.19,48.3 98.22,48.3 98.25,48.28 101.69,46.06 105.23,43.99 105.56,43.81 105.91,43.66 116.92,39.21 116.95,39.19 119.17,36.97 119.19,36.94 119.2,36.9 119.2,35.5 119.19,35.46 119.17,35.43 118.67,34.93 118.64,34.91 118.6,34.9
GND_SIGNAL_B on BOTTOM: outline of 160 points within 74.8,8.1 123.1,29.1
GND_SIGNAL_C on BOTTOM: 57.3,13.4 57.23,13.43 57.2,13.5 57.2,18.9 57.21,18.94 57.23,18.97 57.33,19.07 57.36,19.09 57.4,19.1 58.56,19.1 58.8,19.34 58.8,20.9 58.81,20.94 58.83,20.97 59.6,21.74 59.6,23 59.63,23.07 59.7,23.1 61.46,23.1 61.6,23.24 61.6,26.56 61.36,26.8 60,26.8 59.96,26.81 59.93,26.83 59.63,27.13 59.61,27.16 59.6,27.2 59.6,29.2 59.63,29.27 59.7,29.3 65.76,29.3 66.1,29.64 66.1,31.7 66.13,31.77 66.2,31.8 67.8,31.8 67.87,31.77 67.9,31.7 67.9,27.8 67.89,27.76 67.87,27.73 67.27,27.13 67.24,27.11 67.2,27.1 65.24,27.1 63.5,25.36 63.5,21.5 63.49,21.46 63.47,21.43 61.6,19.56 61.6,13.8 61.59,13.76 61.57,13.73 61.27,13.43 61.24,13.41 61.2,13.4
GND_SIGNAL_D on BOTTOM: 57.25,7 57.2,7.01 56.73,7.45 56.15,7.6 56.1,7.6 56.06,7.61 56.03,7.63 55.73,7.93 55.71,7.96 55.7,8 55.7,9.16 55.36,9.5 47.6,9.5 47.56,9.51 47.53,9.53 47.23,9.83 47.21,9.86 47.2,9.9 47.2,11.3 47.23,11.37 47.3,11.4 49.56,11.4 49.8,11.64 49.8,12.4 49.83,12.47 49.9,12.5 50.9,12.5 50.97,12.47 51,12.4 51,11.64 51.24,11.4 58.6,11.4 58.67,11.37 58.7,11.3 58.7,7.5 58.69,7.46 58.67,7.43 58.27,7.03 58.24,7.01 58.2,7
GND_SIGNAL_E on BOTTOM: 20.43,2.83 20.41,2.86 20.4,2.9 20.4,6.7 20.43,6.77 20.5,6.8 23.16,6.8 23.73,7.37 23.76,7.39 23.8,7.4 32.26,7.4 33.3,8.44 33.3,8.8 33.33,8.87 33.4,8.9 33.56,8.9 33.8,9.14 33.8,11.6 33.81,11.64 33.83,11.67 34.43,12.27 34.46,12.29 34.5,12.3 37.46,12.3 38,12.84 38,14.5 38.03,14.57 38.1,14.6 39.5,14.6 39.57,14.57 39.6,14.5 39.6,7.5 39.59,7.46 39.57,7.43 38.57,6.43 38.54,6.41 38.5,6.4 32.94,6.4 32.77,6.23 32.74,6.21 32.7,6.2 24.34,6.2 23.77,5.63 23.74,5.61 23.7,5.6 21.94,5.6 21.6,5.26 21.6,3.44 23.04,2 80.16,2 80.7,2.54 80.7,6.1 80.71,6.14 80.73,6.17 81.23,6.67 81.26,6.69 81.3,6.7 82.1,6.7 82.14,6.69 82.17,6.67 82.67,6.17 82.69,6.14 82.7,6.1 82.7,2 82.69,1.96 82.67,1.93 81.77,1.03 81.74,1.01 81.7,1 22.3,1 22.26,1.01 22.23,1.03 ; 1 cut-out
GND_SIGNAL_H on BOTTOM: 53.9,33.8 53.83,33.83 53.8,33.9 53.8,34.7 53.81,34.74 53.83,34.77 54.13,35.07 54.16,35.09 54.2,35.1 59.66,35.1 61.6,37.04 61.6,39 61.63,39.07 61.7,39.1 63.1,39.1 63.17,39.07 63.2,39 63.2,38.04 63.44,37.8 65.3,37.8 65.37,37.77 65.4,37.7 65.4,37.1 65.37,37.03 65.3,37 63.44,37 60.27,33.83 60.24,33.81 60.2,33.8
GND_SIGNAL_I on BOTTOM: 96.8,39.4 96.73,39.43 96.7,39.5 96.7,39.96 93.76,42.9 82.44,42.9 82.2,42.66 82.2,41.8 82.17,41.73 82.1,41.7 77.3,41.7 77.23,41.73 77.2,41.8 77.2,43.4 77.23,43.47 77.3,43.5 80.16,43.5 80.93,44.27 80.96,44.29 81,44.3 94.6,44.3 94.64,44.29 94.67,44.27 98.27,40.67 98.29,40.64 98.3,40.6 98.3,39.5 98.27,39.43 98.2,39.4
Net_1 on BOTTOM (solid shape): 68,41.7 67.5,41.7 66.1,42.54 66.1,42.66 67.5,43.5 68,43.5
Net_2 on BOTTOM (solid shape): 79.9,42.66 79.9,42.54 78.5,41.7 78,41.7 78,43.5 78.5,43.5
Net_3 on BOTTOM (solid shape): 68,36.5 67.5,36.5 66.1,37.34 66.1,37.46 67.5,38.3 68,38.3
Net_4 on BOTTOM (solid shape): 79.9,37.46 79.9,37.34 78.5,36.5 78,36.5 78,38.3 78.5,38.3
N15968 on BOTTOM: 191.5,5.2 191.46,5.21 191.43,5.23 190.33,6.33 190.31,6.36 190.3,6.4 190.3,8.1 190.31,8.14 190.33,8.17 191.43,9.27 191.46,9.29 191.5,9.3 201,9.3 201.04,9.29 201.07,9.27 202.17,8.17 202.19,8.14 202.2,8.1 202.2,6.4 202.19,6.36 202.17,6.33 201.07,5.23 201.04,5.21 201,5.2
N15972 on BOTTOM: 165.1,14 165.06,14.01 165.03,14.03 159.26,19.8 157.5,19.8 157.43,19.83 157.4,19.9 157.4,21.66 155.08,23.98 155.05,24.05 155.08,24.12 157.73,26.77 157.8,26.8 157.87,26.77 162.64,22 170.26,22 170.9,22.64 170.9,30.2 170.91,30.24 170.93,30.27 171.43,30.77 171.46,30.79 171.5,30.8 176,30.8 176.04,30.79 176.07,30.77 176.57,30.27 176.59,30.24 176.6,30.2 176.6,14.7 176.59,14.66 176.57,14.63 175.97,14.03 175.94,14.01 175.9,14
N16070 on BOTTOM: 36.5,31.2 36.46,31.21 36.43,31.23 35.43,32.23 35.41,32.26 35.4,32.3 35.4,57.36 34.26,58.5 29.9,58.5 29.83,58.53 29.8,58.6 29.8,63.3 29.81,63.34 29.83,63.37 30.33,63.87 30.36,63.89 30.4,63.9 41.1,63.9 41.14,63.89 41.17,63.87 46.14,58.9 51.2,58.9 51.24,58.89 51.27,58.87 52.27,57.87 52.29,57.84 52.3,57.8 52.3,52.9 52.29,52.86 52.27,52.83 50.2,50.76 50.2,45.7 50.19,45.66 50.17,45.63 41.7,37.16 41.7,32.1 41.69,32.06 41.67,32.03 40.87,31.23 40.84,31.21 40.8,31.2
N16078 on BOTTOM: 8.3,28.4 8.26,28.41 8.23,28.43 7.63,29.03 7.61,29.06 7.6,29.1 7.6,36.5 7.61,36.54 7.63,36.57 13.2,42.14 13.2,84.62 10.93,86.89 10.91,86.92 10.9,86.96 10.9,106.12 10.91,106.16 10.95,106.2 12,106.5 13.05,106.2 13.09,106.16 13.1,106.12 13.1,88.68 18.67,83.11 18.69,83.08 18.7,83.04 18.7,73.03 21.93,69.8 24.4,69.8 24.44,69.79 24.47,69.77 25.77,68.47 25.79,68.44 25.8,68.4 25.8,65.6 25.77,65.53 25.7,65.5 21.34,65.5 20.2,64.36 20.2,28.8 20.19,28.76 20.17,28.73 19.87,28.43 19.84,28.41 19.8,28.4
N16406 on BOTTOM: 144,4.7 137.64,7.34 135,13.7 135,17.9 135.03,17.97 135.1,18 138.9,18 138.97,17.97 139,17.9 139,13.7 139.25,12.14 139.97,10.74 140.01,10.71 140.05,10.7 157.16,10.7 157.4,10.94 157.4,12.1 157.43,12.17 157.5,12.2 158.9,12.2 158.97,12.17 159,12.1 159,10.94 159.24,10.7 178.76,10.7 188.33,20.27 188.36,20.29 188.4,20.3 201,20.3 201.04,20.29 201.07,20.27 202.17,19.17 202.19,19.14 202.2,19.1 202.2,17.4 202.19,17.36 202.17,17.33 201.07,16.23 201.04,16.21 201,16.2 192.44,16.2 180.97,4.73 180.94,4.71 180.9,4.7
N16406 on BOTTOM: 129.3,34.4 129.23,34.43 129.2,34.5 129.2,39.2 129.23,39.27 129.3,39.3 132.8,39.3 132.84,39.29 132.87,39.27 133.67,38.47 133.69,38.44 133.7,38.4 133.7,34.5 133.67,34.43 133.6,34.4
N16414 on BOTTOM: 23.63,73.8 23.59,73.81 23.56,73.83 22.93,74.46 22.91,74.49 22.9,74.53 22.9,86.66 20.76,88.8 17.48,88.8 17.36,88.8 17.24,88.81 17.21,88.82 17.18,88.84 16.37,89.65 16.35,89.68 16.34,89.72 16.34,106.12 16.35,106.16 16.39,106.2 18.41,106.25 19.44,104.5 19.44,91.6 23.87,87.17 23.89,87.14 23.9,87.1 23.9,76.34 24.97,75.27 24.99,75.24 25,75.2 25,74.4 24.99,74.36 24.97,74.33 24.47,73.83 24.44,73.81 24.4,73.8
N16590 on BOTTOM: 117.5,27 117.43,27.03 117.4,27.1 117.4,28 117.43,28.07 117.5,28.1 126.46,28.1 129.3,30.94 129.3,32.6 129.33,32.67 129.4,32.7 130.6,32.7 130.67,32.67 130.7,32.6 130.7,30.4 130.69,30.36 130.67,30.33 127.37,27.03 127.34,27.01 127.3,27
N23336 on BOTTOM: 157.5,14.2 157.43,14.23 157.4,14.3 157.4,17.7 157.43,17.77 157.5,17.8 158.9,17.8 158.97,17.77 159,17.7 159,14.3 158.97,14.23 158.9,14.2
N24888 on BOTTOM: 9.4,14.9 9.36,14.91 9.33,14.93 8.26,16 3.5,16 3.46,16.01 3.43,16.03 3.03,16.43 3.01,16.46 3,16.5 3,43.7 3.01,43.74 3.03,43.77 3.4,44.14 3.4,45.5 3.43,45.57 3.5,45.6 5.46,45.6 5.9,46.04 5.9,48.2 5.93,48.27 6,48.3 6.8,48.3 6.87,48.27 6.9,48.2 6.9,45.6 6.89,45.56 6.87,45.53 5.87,44.53 5.84,44.51 5.8,44.5 4.2,44.5 4.2,43.9 4.19,43.86 4.17,43.83 3.6,43.26 3.6,16.74 3.84,16.5 8.5,16.5 8.54,16.49 8.57,16.47 9.54,15.5 11.66,15.5 11.9,15.74 11.9,16.8 11.93,16.87 12,16.9 12.5,16.9 12.57,16.87 12.6,16.8 12.6,15.74 12.84,15.5 17.76,15.5 18,15.74 18,16.8 18.03,16.87 18.1,16.9 18.6,16.9 18.67,16.87 18.7,16.8 18.7,15.4 18.69,15.36 18.67,15.33 18.27,14.93 18.24,14.91 18.2,14.9
N24910 on BOTTOM: 34.8,12.7 34.73,12.73 34.7,12.8 34.7,13.86 34.46,14.1 30.14,14.1 29.9,13.86 29.9,13.1 29.87,13.03 29.8,13 28.4,13 28.33,13.03 28.3,13.1 28.3,13.86 28.06,14.1 22.3,14.1 22.26,14.11 22.23,14.13 19.06,17.3 17.04,17.3 16.8,17.06 16.8,16 16.77,15.93 16.7,15.9 16.2,15.9 16.13,15.93 16.1,16 16.1,17.06 15.86,17.3 10.94,17.3 10.7,17.06 10.7,16 10.67,15.93 10.6,15.9 10.1,15.9 10.03,15.93 10,16 10,17.4 10.01,17.44 10.03,17.47 10.63,18.07 10.66,18.09 10.7,18.1 19.4,18.1 19.44,18.09 19.47,18.07 22.64,14.9 34.8,14.9 34.84,14.89 34.87,14.87 35.47,14.27 35.49,14.24 35.5,14.2 35.5,12.8 35.47,12.73 35.4,12.7
N25221 on BOTTOM: 6,50.3 5.93,50.33 5.9,50.4 5.9,52.56 5.46,53 3.1,53 3.03,53.03 3,53.1 3,75.2 3.01,75.24 3.03,75.27 3.53,75.77 3.56,75.79 3.6,75.8 4.4,75.8 4.44,75.79 4.47,75.77 4.97,75.27 4.99,75.24 5,75.2 5,74.4 4.99,74.36 4.97,74.33 3.8,73.16 3.8,54.34 4.04,54.1 5.8,54.1 5.84,54.09 5.87,54.07 6.87,53.07 6.89,53.04 6.9,53 6.9,50.4 6.87,50.33 6.8,50.3
N419198 on BOTTOM: 29.9,51.5 29.83,51.53 29.8,51.6 29.8,56.4 29.83,56.47 29.9,56.5 31.3,56.5 31.37,56.47 31.4,56.4 31.4,51.6 31.37,51.53 31.3,51.5
N419202 on BOTTOM: 29.9,44.5 29.83,44.53 29.8,44.6 29.8,49.4 29.83,49.47 29.9,49.5 31.3,49.5 31.37,49.47 31.4,49.4 31.4,44.6 31.37,44.53 31.3,44.5
N419206 on BOTTOM: 29.9,37.5 29.83,37.53 29.8,37.6 29.8,42.4 29.83,42.47 29.9,42.5 31.3,42.5 31.37,42.47 31.4,42.4 31.4,37.6 31.37,37.53 31.3,37.5
N419210 on BOTTOM: 29.9,30.5 29.83,30.53 29.8,30.6 29.8,35.4 29.83,35.47 29.9,35.5 31.3,35.5 31.37,35.47 31.4,35.4 31.4,30.6 31.37,30.53 31.3,30.5
N419378 on BOTTOM: 24.3,44.5 24.23,44.53 24.2,44.6 24.2,49.4 24.23,49.47 24.3,49.5 25.7,49.5 25.77,49.47 25.8,49.4 25.8,44.6 25.77,44.53 25.7,44.5
N419402 on BOTTOM: 24.3,37.5 24.23,37.53 24.2,37.6 24.2,42.4 24.23,42.47 24.3,42.5 25.7,42.5 25.77,42.47 25.8,42.4 25.8,37.6 25.77,37.53 25.7,37.5
N419426 on BOTTOM: 24.3,30.5 24.23,30.53 24.2,30.6 24.2,35.4 24.23,35.47 24.3,35.5 25.7,35.5 25.77,35.47 25.8,35.4 25.8,30.6 25.77,30.53 25.7,30.5
N419540 on BOTTOM: 24.3,23.5 24.23,23.53 24.2,23.6 24.2,28.4 24.23,28.47 24.3,28.5 25.7,28.5 25.77,28.47 25.8,28.4 25.8,23.6 25.77,23.53 25.7,23.5
N420408 on BOTTOM: 63.8,85.6 63.76,85.61 63.73,85.63 59.06,90.3 57.4,90.3 57.36,90.31 57.33,90.33 56.53,91.13 56.51,91.16 56.5,91.2 56.5,105 57.09,106.41 58.5,107 60.1,107 60.14,106.99 60.17,106.97 69.47,97.67 69.49,97.64 69.5,97.6 69.5,90.84 71.74,88.6 78.9,88.6 78.94,88.59 78.97,88.57 79.47,88.07 79.49,88.04 79.5,88 79.5,86.2 79.49,86.16 79.47,86.13 78.97,85.63 78.94,85.61 78.9,85.6
N420417 on BOTTOM: 25.7,82.2 25.63,82.23 25.6,82.3 25.6,84.8 25.61,84.84 25.63,84.87 26.53,85.77 26.56,85.79 26.6,85.8 28.76,85.8 29.2,86.24 29.2,95.2 29.21,95.24 29.23,95.27 31,97.04 31,105 33,107 35,105 35,83.3 34.99,83.26 34.97,83.23 33.97,82.23 33.94,82.21 33.9,82.2
N424661 on BOTTOM: 115.9,23.9 115.86,23.91 115.83,23.93 110.76,29 106.4,29 106.36,29.01 106.33,29.03 105.73,29.63 105.71,29.66 105.7,29.7 105.7,32.9 105.73,32.97 105.8,33 107.2,33 107.27,32.97 107.3,32.9 107.3,30.74 107.94,30.1 111.3,30.1 111.34,30.09 111.37,30.07 116.44,25 121.6,25 121.67,24.97 121.7,24.9 121.7,24 121.67,23.93 121.6,23.9
N424705 on BOTTOM: 99.6,30.6 99.56,30.61 99.53,30.63 98.96,31.2 96.8,31.2 96.73,31.23 96.7,31.3 96.7,32.2 96.73,32.27 96.8,32.3 100.36,32.3 104.13,36.07 104.16,36.09 104.2,36.1 107.2,36.1 107.27,36.07 107.3,36 107.3,35.1 107.27,35.03 107.2,35 104.84,35 100.47,30.63 100.44,30.61 100.4,30.6
N424749 on BOTTOM: 96.8,34.2 96.73,34.23 96.7,34.3 96.7,37.3 96.73,37.37 96.8,37.4 98.2,37.4 98.27,37.37 98.3,37.3 98.3,34.3 98.27,34.23 98.2,34.2
N424773 on BOTTOM: 105.8,37.3 105.73,37.33 105.7,37.4 105.7,38.3 105.73,38.37 105.8,38.4 110.8,38.4 110.87,38.37 110.9,38.3 110.9,37.4 110.87,37.33 110.8,37.3
N427169 on BOTTOM: 91.1,19.6 91.03,19.63 91,19.7 91,24.56 90.66,24.9 90.14,24.9 89.8,24.56 89.8,20.2 89.79,20.16 89.77,20.13 89.47,19.83 89.44,19.81 89.4,19.8 88.5,19.8 88.46,19.81 88.43,19.83 88.13,20.13 88.11,20.16 88.1,20.2 88.1,24.8 88.11,24.84 88.13,24.87 89.73,26.47 89.76,26.49 89.8,26.5 91,26.5 91.04,26.49 91.07,26.47 92.57,24.97 92.59,24.94 92.6,24.9 92.6,21.44 92.84,21.2 96,21.2 96.07,21.17 96.1,21.1 96.1,19.7 96.07,19.63 96,19.6
N427204 on BOTTOM: 97.9,22.8 97.86,22.81 97.83,22.83 97.36,23.3 94.6,23.3 94.53,23.33 94.5,23.4 94.5,25.6 94.53,25.67 94.6,25.7 96,25.7 96.07,25.67 96.1,25.6 96.1,25.44 96.44,25.1 98.4,25.1 98.44,25.09 98.47,25.07 99.27,24.27 99.29,24.24 99.3,24.2 99.3,23.4 99.29,23.36 99.27,23.33 98.77,22.83 98.74,22.81 98.7,22.8
N427457 on BOTTOM: 83.4,19.8 83.36,19.81 83.33,19.83 83.03,20.13 83.01,20.16 83,20.2 83,24.06 82.16,24.9 80.04,24.9 78.07,22.93 78.04,22.91 78,22.9 76.8,22.9 76.76,22.91 76.73,22.93 76.23,23.43 76.21,23.46 76.2,23.5 76.2,24.1 76.21,24.14 76.23,24.17 76.73,24.67 76.76,24.69 76.8,24.7 77.66,24.7 79.43,26.47 79.46,26.49 79.5,26.5 83,26.5 83.04,26.49 83.07,26.47 84.67,24.87 84.69,24.84 84.7,24.8 84.7,20.2 84.69,20.16 84.67,20.13 84.37,19.83 84.34,19.81 84.3,19.8
N431073 on BOTTOM: 73.2,14 73.16,14.01 73.13,14.03 72.83,14.33 72.81,14.36 72.8,14.4 72.8,16.7 72.83,16.77 72.9,16.8 73.9,16.8 73.97,16.77 74,16.7 74,14.1 73.97,14.03 73.9,14
N438066 on BOTTOM: 104,2.7 103.96,2.71 103.93,2.73 103.63,3.03 103.61,3.06 103.6,3.1 103.6,3.98 103.61,4.02 103.63,4.05 105.25,5.67 105.28,5.69 105.32,5.7 117.06,5.7 118.33,6.97 118.36,6.99 118.4,7 130.4,7 130.44,6.99 130.47,6.97 131.07,6.37 131.09,6.34 131.1,6.3 131.1,5.5 131.09,5.46 131.07,5.43 130.47,4.83 130.44,4.81 130.4,4.8 120.44,4.8 118.37,2.73 118.34,2.71 118.3,2.7
N438142 on BOTTOM: 110.6,11.3 110.56,11.31 110.53,11.33 110.03,11.83 110.01,11.86 110,11.9 110,12.7 110.01,12.74 110.03,12.77 110.53,13.27 110.56,13.29 110.6,13.3 112.86,13.3 113.3,13.74 113.3,15.46 112.96,15.8 111.8,15.8 111.73,15.83 111.7,15.9 111.7,16.6 111.71,16.64 111.73,16.67 112,16.94 112,19.26 110.76,20.5 107.1,20.5 107.06,20.51 107.03,20.53 105.23,22.33 105.21,22.36 105.2,22.4 105.2,24.2 105.21,24.24 105.23,24.27 105.83,24.87 105.86,24.89 105.9,24.9 106.7,24.9 106.74,24.89 106.77,24.87 107.37,24.27 107.39,24.24 107.4,24.2 107.4,23.54 108.04,22.9 111.1,22.9 111.14,22.89 111.17,22.87 115.87,18.17 115.89,18.14 115.9,18.1 115.9,11.9 115.89,11.86 115.87,11.83 115.37,11.33 115.34,11.31 115.3,11.3
N438200 on BOTTOM: 103.8,11.3 103.76,11.31 103.73,11.33 102.53,12.53 102.51,12.56 102.5,12.6 102.5,15.6 102.53,15.67 102.6,15.7 104.2,15.7 104.24,15.69 104.27,15.67 105.14,14.8 106.86,14.8 109.4,17.34 109.4,18.7 109.41,18.74 109.43,18.77 109.93,19.27 109.96,19.29 110,19.3 110.8,19.3 110.84,19.29 110.87,19.27 111.37,18.77 111.39,18.74 111.4,18.7 111.4,17.3 111.39,17.26 111.37,17.23 107,12.86 107,12 106.99,11.96 106.97,11.93 106.37,11.33 106.34,11.31 106.3,11.3
N456904 on BOTTOM: 1.6,13.7 1.56,13.71 1.53,13.73 1.03,14.23 1.01,14.26 1,14.3 1,100.8 1.01,100.84 1.03,100.87 2.13,101.97 2.16,101.99 2.2,102 3.7,102 3.77,101.97 3.8,101.9 3.8,100.9 3.79,100.86 3.77,100.83 1.6,98.66 1.6,15.74 2.54,14.8 7,14.8 7.07,14.77 7.1,14.7 7.1,13.8 7.07,13.73 7,13.7
N469207 on BOTTOM: 24.3,51.5 24.23,51.53 24.2,51.6 24.2,56.4 24.23,56.47 24.3,56.5 25.7,56.5 25.77,56.47 25.8,56.4 25.8,51.6 25.77,51.53 25.7,51.5
N469217 on BOTTOM: 24.3,58.5 24.23,58.53 24.2,58.6 24.2,63.4 24.23,63.47 24.3,63.5 25.7,63.5 25.77,63.47 25.8,63.4 25.8,58.6 25.77,58.53 25.7,58.5
N493941 on BOTTOM: 75,48.4 74.93,48.43 74.9,48.5 74.9,52.3 74.91,52.34 74.93,52.37 75.33,52.77 75.36,52.79 75.4,52.8 76,52.8 76.04,52.79 76.07,52.77 76.47,52.37 76.49,52.34 76.5,52.3 76.5,48.5 76.47,48.43 76.4,48.4
N504842 on BOTTOM: 85.4,54.1 85.36,54.11 85.33,54.13 82.76,56.7 68,56.7 67.96,56.71 67.93,56.73 58.76,65.9 50.4,65.9 50.36,65.91 50.33,65.93 36.26,80 26.8,80 26.76,80.01 26.73,80.03 26.43,80.33 26.41,80.36 26.4,80.4 26.4,81.2 26.41,81.24 26.43,81.27 26.73,81.57 26.76,81.59 26.8,81.6 36.9,81.6 36.94,81.59 36.97,81.57 51.04,67.5 59.4,67.5 59.44,67.49 59.47,67.47 68.64,58.3 83.4,58.3 83.44,58.29 83.47,58.27 86.47,55.27 86.49,55.24 86.5,55.2 86.5,54.6 86.49,54.56 86.47,54.53 86.07,54.13 86.04,54.11 86,54.1
N682614 on BOTTOM: 80.9,36.7 80.83,36.73 80.8,36.8 80.8,39.5 80.83,39.57 80.9,39.6 81.9,39.6 81.97,39.57 82,39.5 82,36.8 81.97,36.73 81.9,36.7

Small or netless copper shapes (teardrops, artwork), in the pictures only: 111 on BOTTOM

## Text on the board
Ref Des/Silkscreen Bottom: B | C | E | 1 | 16 | 8 | 9 | A | K | Q4 | Q2 | G | Q1 | Q3 | D2 | Q5 | IC1 | RTH1 | TP2 | R19 | D5 | J27 | R13 | R23 | R20 | R3 | R4 | C5 | R2 | R6 | R10 | R15 | R18 | R22 | R24 | J26 | R27 | R7 | R11 | D4 | R5 | R9 | R12 | R17 | R21 | R29 | C6 | R16 | J25 | R31 | R47 | C17 | R62 | C7 | TP5 | D7 | R40 | R42 | C18 | J21 | R38 | J20 | C14 | J18 | J24 | J19 | C13 | R41 | R37 | C11 | C10 | R25 | TP3 | R55 | C9 | J17 | D9 | J16 | C19 | J22 | R54 | C21 | C20 | C26 | R56 | D11 | R53 | J28 | R50 | R44 | R36 | R52 | TP1 | D12 | D8 | R34 | TP4 | D10 | R43 | R35 | R33 | C15 | R26 | R28 | D1 | D6 | D3 | R1 | R8 | POWER_GND | +18VG | +5V | +18VF | SIGNAL_GND
Ref Des/Silkscreen Top: J3 | J7 | J6 | R14 | C2 | C1 | 2 | 1 | SENSOR | JP1 | CN2 | 3 | J10 | CN4 | J12 | J13 | J14 | L1 | CN3 | 4 | DEBUG | FAN | CN5 | CN6 | C4 | IC3 | C8 | 5 | IC2 | C16 | 8 | C3 | J2 | J1 | GND | SCL | SDA | +5V | C24 | J8 | C25 | J15 | Vout | J5 | Vin | C23 | C22 | C27 | T1 | BZ1 | J11 | C12 | J9 | R32 | RV1 | F1 | 12.5A/250VAC | CN1_2 | CN1_1 | IH Cooker Heating Board
